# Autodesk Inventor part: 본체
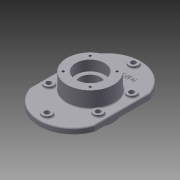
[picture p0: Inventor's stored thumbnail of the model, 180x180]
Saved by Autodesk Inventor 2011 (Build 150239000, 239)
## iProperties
Created: 2015-02
Part Number: 본체
Material: 알루미늄-6061
Document SubType Name: Modeling
Designer: Administrator
Mass: 1637.29 g
Surface Area: 924.766 cm^2
Volume: 604.167 cm^3
Density: 2.71 g/cm^3
Author: Administrator
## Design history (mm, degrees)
sketch "스케치1"
  geometry: C1 r 50 at (0, 0); 1 further point
  constraints: 1 centre point, 1 coincident
  dimensions: "d0" = 100 diameter of C1
extrude "돌출1" new body sketch "스케치1" distance "d1" = 23; taper "d2" = 0 deg
sketch "스케치2"
  geometry: L1 (-70, 0)-(-70, -60); L2 (70, -60)-(70, 60); L3 (-70, 60)-(-70, 0); A1 r 74 centre (0, -36) between (-70, -60) and (70, -60); A2 r 74 centre (0, 36) between (70, 60) and (-70, 60)
  constraints: 6 end point, 4 point on circle, 2 centre point
extrude "돌출2" join sketch "스케치2" distance "d3" = 12; taper "d4" = 0 deg
sketch "스케치3"
  geometry: C1 r 50 at (0, 0); 1 further point
  constraints: 1 centre point, 1 coincident
extrude "돌출3" join sketch "스케치3" distance "d5" = 35; taper "d6" = 0 deg
sketch "스케치4"
  geometry: L1 (-70, -60)-(-70, 60) reference; L2 (70, 60)-(70, -60) reference; L3 (-70, 0)-(70, 0); L4 (0, 110)-(0, -110); L5 (-70, 36)-(-53, 36); L6 (-70, -36)-(-53, -36); L7 (70, 36)-(53, 36); L8 (70, -36)-(53, -36); C1 r 10 at (0, -93); C2 r 10 at (0, 93); C3 r 10 at (-53, 36); C4 r 10 at (-53, -36); C5 r 10 at (53, 36); C6 r 10 at (53, -36); A1 r 74 centre (0, -36) between (-70, -60) and (70, -60) reference; A2 r 74 centre (0, 36) between (70, 60) and (-70, 60) reference; 2 further points
  constraints: 12 end point, 6 centre point, 6 coincident, 6 point on line, 2 midpoint, 2 point on circle
  dimensions: "d7" = 17 distance of L4.end point (0, -93); "d8" = 17 distance of L4.start point (0, 93)
extrude "돌출4" join sketch "스케치4" distance "d9" = 5; taper "d10" = 0 deg
sketch "스케치5"
  geometry: C1 r 10 at (0, 0) reference; C2 r 10 at (-53, -57) reference; C3 r 10 at (-53, -129) reference; C4 r 10 at (0, -186) reference; C5 r 10 at (53, -129) reference; C6 r 10 at (53, -57) reference; 1 further point
hole "Hole1" sketch "스케치5" at (0, 0), (-53, -57), (-53, -129), (0, -186), (53, -129), (53, -57) diameter "d11" = 11; stored, may be unused: countersink angle "d15" = 90 deg, drill point angle "d17" = 118 deg; dims "d12" = 6, "d13" = 4, "d14" = 2, "d16" = 8
sketch "스케치6"
  geometry: C1 r 50 at (0, 0) reference; C2 r 31 at (0, 0)
  constraints: 1 centre point, 1 coincident
extrude "돌출5" cut sketch "스케치6" distance "d18" = 22; taper "d19" = 0 deg
sketch "스케치7"
  geometry: C1 r 50 at (0, 0) reference; C2 r 31 at (0, 0)
  constraints: 1 centre point, 1 coincident
extrude "돌출6" cut sketch "스케치7" distance "d20" = 22; taper "d21" = 0 deg
sketch "스케치8"
  geometry: C1 r 31 at (0, 0) reference; C2 r 22.5 at (0, 0)
  constraints: 1 centre point, 1 coincident
extrude "돌출7" cut sketch "스케치8" stored distance "d22" = 22; taper "d23" = 0 deg
sketch "스케치9"
  geometry: L1 (0, 0)-(28.991, 28.991); C1 r 50 at (0, 0) reference; 1 further point
  constraints: 2 coincident, 2 end point, 3 other
sketch "스케치10"
  geometry: L1 (0, 0)-(28.991, 28.991); C1 r 50 at (0, 0) reference; 1 further point
  constraints: 2 coincident, 2 end point, 3 other
hole "Hole2" sketch "스케치10" at (28.991, 28.991) diameter "d24" = 4.917; stored, may be unused: countersink angle "d28" = 90 deg, drill point angle "d30" = 118 deg; dims "d25" = 10, "d26" = 4, "d27" = 2, "d29" = 13
hole "Hole3" sketch "스케치9" diameter "d34" = 4.917; stored, may be unused: countersink angle "d38" = 90 deg, drill point angle "d40" = 118 deg; dims "d35" = 10, "d36" = 4, "d37" = 2, "d39" = 13
fillet "모깎기1" dims "d44" = 3
sketch "스케치11"
  geometry: A1 r 53 centre (0, 0) between (-47.02, 24.457) and (-47.02, -24.457) reference; 1 further point
  constraints: 1 vertical alignment, 1 other
  dimensions: "d45" = 65 distance of A1.centre point (0, 65)
feature "엠보싱1" sketch "스케치11" dims "d46" = 1, "d47" = 0
fillet "모깎기2" dims "d48" = 0.3
node "솔리드1"
pattern_circular "원형 패턴1" dims angle "d32" = 360 deg
pattern_circular "원형 패턴2" dims angle "d42" = 360 deg
node "투영된 루프1"
node "투영된 루프2"
node "투영된 루프3"
node "투영된 루프4"
node "투영된 루프5"
